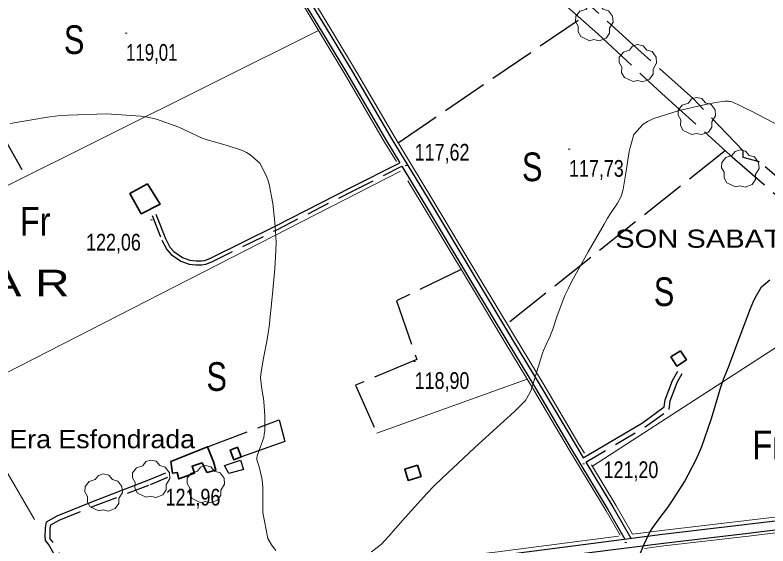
# Model space of a CAD drawing. Extents: x 487425 to 492029, y 4383576 to 4386788.
# Drawn here: x 489030 to 489424, y 4385465.2 to 4385743 of the extents above; entities that cross this region are included whole.
import ezdxf
from ezdxf.enums import TextEntityAlignment as Align

# ---------------------------------------------------------------- set-up
doc = ezdxf.new("R2010")
doc.units = 0
doc.header["$LTSCALE"] = 4
doc.linetypes.add('LONG_DASHED', pattern=[7.5, 6, -1.5])
doc.linetypes.add('MEDIUM_DASHED', pattern=[4.5, 3, -1.5])
for name, color, linetype, lineweight in [('21', 7, 'Continuous', 25), ('25', 7, 'LONG_DASHED', 25), ('29', 7, 'Continuous', 13), ('36', 7, 'Continuous', 25), ('38', 7, 'Continuous', 25), ('47', 7, 'Continuous', 35), ('51', 7, 'Continuous', 13), ('7', 7, 'Continuous', 13), ('8', 7, 'Continuous', 25), ('9', 7, 'Continuous', 13)]:
    doc.layers.add(name, color=color, linetype=linetype, lineweight=lineweight)
doc.layers.add('31', color=7, linetype='Continuous')
doc.layers.add('5', color=7, linetype='Continuous')

msp = doc.modelspace()

# ---------------------------------------------------------------- linework, layer by layer
at = {"layer": '21'}
msp.add_lwpolyline([(489139.64, 4385507.26), (489147.92, 4385510.02), (489149.59, 4385505.27), (489141.84, 4385503.18)], close=True, dxfattribs=at)
at = {"layer": '25'}
for p, q in [((489230.49, 4385676.18), (489325.89, 4385741.14)), ((489401.74, 4385672.05), (489287.47, 4385581.38))]:
    msp.add_line(p, q, dxfattribs=at)
for points in [[(489440.72, 4385647.8), (489419.55, 4385666.12), (489411.02, 4385668.4), (489411.06, 4385671.92), (489385.11, 4385699.07), (489357.64, 4385723.62), (489317.54, 4385760.31), (489289.47, 4385785.39), (489257.02, 4385815.16), (489220.69, 4385845.74), (489191.36, 4385872.85), (489168.69, 4385891.87), (489144.7, 4385919.22), (489122.97, 4385941.6), (489239.75, 4386043.95), (489321.93, 4386119.99), (489486.42, 4385943.37)], [(489115.71, 4385929.31), (489159.69, 4385891.74), (489196.81, 4385857.49), (489250.5, 4385809.01), (489294.68, 4385768.67), (489335.01, 4385733.1), (489368.49, 4385701.89), (489404.14, 4385669.9), (489456.29, 4385624.52), (489481.26, 4385603.45)], [(489142.46, 4385812.11), (488991.66, 4385734.98), (489035.67, 4385658.64)], [(489263.48, 4385609.86), (489229.67, 4385593.49), (489240.2, 4385562.68), (489208.24, 4385549.32), (489219.72, 4385523.38)], [(489128.97, 4385516.4), (489168.19, 4385531.17), (489171.14, 4385519.88), (489148.32, 4385511.73)]]:
    msp.add_lwpolyline(points, dxfattribs=at)
at = {"layer": '29'}
for points in [[(489330.6, 4385729.56), (489326.06, 4385731.68), (489324.65, 4385734.22), (489324.75, 4385737.2), (489323.38, 4385739.61), (489323.42, 4385742.36), (489325.58, 4385744.96), (489328.77, 4385745.96), (489330.42, 4385748.15), (489332.99, 4385748.98), (489335.85, 4385748.33), (489337.8, 4385746.06), (489340.61, 4385745.24), (489342.74, 4385742.39), (489342.98, 4385739.26), (489341.1, 4385736.11), (489341.1, 4385733.43), (489339.28, 4385730.82), (489335.66, 4385729.48), (489332.89, 4385730.11)], [(489353.39, 4385708.15), (489348.85, 4385710.27), (489347.44, 4385712.81), (489347.54, 4385715.79), (489346.17, 4385718.2), (489346.21, 4385720.95), (489348.37, 4385723.55), (489351.56, 4385724.55), (489353.21, 4385726.74), (489355.78, 4385727.57), (489358.64, 4385726.92), (489360.59, 4385724.65), (489363.4, 4385723.83), (489365.53, 4385720.98), (489365.77, 4385717.85), (489363.89, 4385714.7), (489363.89, 4385712.02), (489362.07, 4385709.41), (489358.45, 4385708.07), (489355.68, 4385708.7)], [(489384.21, 4385680.49), (489379.67, 4385682.61), (489378.26, 4385685.15), (489378.36, 4385688.13), (489376.99, 4385690.54), (489377.03, 4385693.29), (489379.19, 4385695.89), (489382.38, 4385696.89), (489384.03, 4385699.08), (489386.6, 4385699.91), (489389.46, 4385699.26), (489391.41, 4385696.99), (489394.22, 4385696.17), (489396.35, 4385693.32), (489396.59, 4385690.19), (489394.71, 4385687.04), (489394.71, 4385684.36), (489392.89, 4385681.75), (489389.27, 4385680.41), (489386.5, 4385681.04)], [(489407, 4385653.07), (489402.46, 4385655.19), (489401.05, 4385657.73), (489401.15, 4385660.71), (489399.78, 4385663.12), (489399.82, 4385665.87), (489401.98, 4385668.47), (489405.17, 4385669.47), (489406.82, 4385671.66), (489409.39, 4385672.49), (489412.25, 4385671.84), (489414.2, 4385669.57), (489417.01, 4385668.75), (489419.14, 4385665.9), (489419.38, 4385662.77), (489417.5, 4385659.62), (489417.5, 4385656.94), (489415.68, 4385654.33), (489412.06, 4385652.99), (489409.29, 4385653.62)], [(489098.62, 4385490.7), (489094.08, 4385492.82), (489092.67, 4385495.36), (489092.77, 4385498.34), (489091.4, 4385500.75), (489091.44, 4385503.5), (489093.6, 4385506.1), (489096.79, 4385507.1), (489098.44, 4385509.29), (489101.01, 4385510.12), (489103.87, 4385509.47), (489105.82, 4385507.2), (489108.63, 4385506.38), (489110.76, 4385503.53), (489111, 4385500.4), (489109.12, 4385497.25), (489109.12, 4385494.57), (489107.3, 4385491.96), (489103.68, 4385490.62), (489100.91, 4385491.25)], [(489127.24, 4385487.83), (489122.7, 4385489.95), (489121.29, 4385492.49), (489121.39, 4385495.47), (489120.02, 4385497.88), (489120.06, 4385500.63), (489122.22, 4385503.23), (489125.41, 4385504.23), (489127.06, 4385506.42), (489129.63, 4385507.25), (489132.49, 4385506.6), (489134.44, 4385504.33), (489137.25, 4385503.51), (489139.38, 4385500.66), (489139.62, 4385497.53), (489137.74, 4385494.38), (489137.74, 4385491.7), (489135.92, 4385489.09), (489132.3, 4385487.75), (489129.53, 4385488.38)], [(489073.78, 4385483.49), (489069.24, 4385485.61), (489067.83, 4385488.15), (489067.93, 4385491.13), (489066.56, 4385493.54), (489066.6, 4385496.29), (489068.76, 4385498.89), (489071.95, 4385499.89), (489073.6, 4385502.08), (489076.17, 4385502.91), (489079.03, 4385502.26), (489080.98, 4385499.99), (489083.79, 4385499.17), (489085.92, 4385496.32), (489086.16, 4385493.19), (489084.28, 4385490.04), (489084.28, 4385487.36), (489082.46, 4385484.75), (489078.84, 4385483.41), (489076.07, 4385484.04)]]:
    msp.add_lwpolyline(points, close=True, dxfattribs=at)
at = {"layer": '36'}
for points in [[(489281.47, 4385459.94), (489327.29, 4385465.95), (489368.77, 4385471.33), (489413.1, 4385476.52), (489451.09, 4385481.12), (489465.77, 4385483.2), (489481.59, 4385484.6), (489488.9, 4385485.86), (489497.14, 4385486.32), (489505.02, 4385487.33), (489519.98, 4385489.49), (489545.69, 4385492.34), (489575.79, 4385496.13), (489620.25, 4385502.45), (489667.37, 4385509.94), (489711.04, 4385516.12), (489752.58, 4385522.55), (489794.27, 4385529.5), (489845.5, 4385537.62), (489881.67, 4385542.39)], [(489327.89, 4385461.33), (489369.34, 4385466.71), (489413.65, 4385471.9), (489451.69, 4385476.5), (489466.31, 4385478.58), (489482.19, 4385479.98), (489489.43, 4385481.23), (489497.56, 4385481.67), (489505.65, 4385482.71), (489520.57, 4385484.87), (489546.24, 4385487.72), (489576.41, 4385491.51), (489620.94, 4385497.84), (489668.06, 4385505.33), (489711.72, 4385511.51), (489753.31, 4385517.94), (489795.03, 4385524.9), (489846.17, 4385533.01), (489882.27, 4385537.77)]]:
    msp.add_lwpolyline(points, dxfattribs=at)
at = {"layer": '38'}
for points in [[(489110.22, 4385925.95), (489110.66, 4385920.71), (489111.24, 4385912.05), (489111.46, 4385905.23), (489111.37, 4385897.37), (489111.4, 4385892.88), (489111.79, 4385886.68), (489112.87, 4385881.22), (489114.23, 4385873.84), (489116.73, 4385865.29), (489118.9, 4385858.42), (489120.71, 4385852.64), (489121.84, 4385848.89), (489125.24, 4385841.78), (489133.79, 4385828.08), (489144.02, 4385811.83), (489152.62, 4385797.75), (489160.99, 4385783.12), (489171.53, 4385764.8), (489183.26, 4385746.28), (489192.23, 4385731.42), (489204.59, 4385710.88), (489224.39, 4385677.11), (489231.34, 4385665.63)], [(489185.74, 4385747.81), (489194.72, 4385732.92), (489207.1, 4385712.37), (489226.9, 4385678.61), (489246.11, 4385646.88), (489271.29, 4385604.73), (489290.36, 4385573.08), (489304.87, 4385549.21), (489323.57, 4385517.56), (489327.36, 4385511.27)], [(489103.71, 4385638.88), (489108.65, 4385626.12), (489111.07, 4385621.52), (489113.13, 4385619.19), (489117.62, 4385616.06), (489121.49, 4385614.67), (489124.76, 4385614.35), (489127.5, 4385614.32), (489129.33, 4385614.57), (489132.2, 4385615.75), (489166.42, 4385632.67), (489205.73, 4385652.7), (489231.34, 4385665.63)], [(489232.41, 4385663.88), (489243.62, 4385645.38), (489268.8, 4385603.23), (489287.87, 4385571.57), (489302.38, 4385547.71), (489321.06, 4385516.06), (489340.28, 4385484.2), (489349.13, 4385468.78)], [(489327.36, 4385511.27), (489358.3, 4385529.64), (489369.78, 4385538.05), (489370.22, 4385541.69), (489374.11, 4385551.76), (489376.77, 4385556.62)], [(489328.72, 4385509.01), (489342.79, 4385485.68), (489352.25, 4385469.19)], [(489065.07, 4385435.14), (489047.55, 4385466.08), (489045.9, 4385468.02), (489045.84, 4385470.57), (489045.88, 4385473.82), (489045.89, 4385474.7), (489046.52, 4385477.78), (489052.06, 4385480.86), (489071.07, 4385488.63), (489099.93, 4385499.7), (489108.96, 4385503.42)]]:
    msp.add_lwpolyline(points, dxfattribs=at)
at = {"layer": '38', "linetype": 'MEDIUM_DASHED'}
for points in [[(489101.8, 4385638.14), (489106.79, 4385625.27), (489109.37, 4385620.34), (489111.76, 4385617.66), (489116.67, 4385614.22), (489121.04, 4385612.66), (489124.65, 4385612.3), (489127.63, 4385612.27), (489129.87, 4385612.58), (489133.05, 4385613.89), (489167.33, 4385630.85), (489206.66, 4385650.88), (489232.41, 4385663.88)], [(489328.72, 4385509.01), (489359.76, 4385527.43), (489372.27, 4385536.59), (489372.81, 4385541.04), (489376.52, 4385550.64), (489379.09, 4385555.35)], [(489067.91, 4385435.52), (489049.59, 4385467.5), (489048.36, 4385468.96), (489048.32, 4385470.59), (489048.36, 4385473.79), (489048.37, 4385474.43), (489048.72, 4385476.16), (489053.14, 4385478.61), (489071.99, 4385486.32), (489100.85, 4385497.39), (489109.9, 4385501.13)]]:
    msp.add_lwpolyline(points, dxfattribs=at)
at = {"layer": '47'}
for points in [[(489099.23, 4385654.69), (489105.93, 4385644.11), (489096.05, 4385639.04), (489090.09, 4385649.69)], [(489378.21, 4385567.34), (489373.19, 4385564.1), (489376.32, 4385559.26), (489381.34, 4385562.5)], [(489111.45, 4385509.38), (489130.75, 4385517.11), (489133.81, 4385509.2), (489135.03, 4385504.91), (489130.37, 4385503.69), (489127.87, 4385508.59), (489122.68, 4385506.93), (489123.91, 4385503.31), (489115.78, 4385500.25), (489114.76, 4385503.64), (489112.43, 4385503.22)], [(489146.42, 4385516.79), (489148.32, 4385511.73), (489144.47, 4385510.28), (489142.57, 4385515.34)], [(489240.62, 4385507.39), (489233.96, 4385505.28), (489235.8, 4385499.49), (489242.46, 4385501.6)]]:
    msp.add_lwpolyline(points, close=True, dxfattribs=at)
at = {"layer": '51'}
for p, q in [((489188.8, 4385734.84), (488956.26, 4385619.12)), ((489481.26, 4385603.45), (489332.15, 4385506.85)), ((489219.4, 4385524.12), (489298.08, 4385552.53))]:
    msp.add_line(p, q, dxfattribs=at)
for points in [[(489229.57, 4385666.3), (489223.38, 4385676.51), (489203.58, 4385710.28), (489191.22, 4385730.81), (489182.26, 4385745.66), (489170.52, 4385764.19), (489159.97, 4385782.54), (489151.61, 4385797.15), (489143.02, 4385811.21), (489132.79, 4385827.46), (489124.21, 4385841.21), (489120.74, 4385848.46), (489119.59, 4385852.3), (489117.78, 4385858.07), (489115.61, 4385864.95), (489113.09, 4385873.57), (489111.72, 4385881), (489110.62, 4385886.53), (489110.23, 4385892.84), (489110.2, 4385897.37), (489110.29, 4385905.22), (489110.07, 4385911.99), (489109.49, 4385920.62), (489109.31, 4385922.77)], [(488777.96, 4385916.34), (488806.25, 4385870.86), (488848.74, 4385800.38), (488874.73, 4385757.32), (488910.35, 4385697.05), (488957.16, 4385617.59), (489002.92, 4385544.3), (489231.79, 4385661.28)], [(489328, 4385513.72), (489325.12, 4385518.49), (489306.42, 4385550.14), (489291.91, 4385574.02), (489272.84, 4385605.66), (489247.66, 4385647.81), (489228.46, 4385679.54), (489208.66, 4385713.3), (489196.27, 4385733.85), (489187.28, 4385748.77)], [(489235.62, 4385656.32), (489242.61, 4385644.77), (489267.79, 4385602.63), (489286.87, 4385570.96), (489301.37, 4385547.11), (489320.05, 4385515.46), (489339.27, 4385483.6), (489346.61, 4385470.82)], [(488871.33, 4385429.34), (489021.81, 4385510.25), (489040.21, 4385478.98)], [(489331.67, 4385507.63), (489344.35, 4385486.6), (489353.16, 4385471.27)], [(489594.86, 4385492.56), (489576.62, 4385489.96), (489546.42, 4385486.17), (489520.77, 4385483.32), (489505.86, 4385481.17), (489497.7, 4385480.12), (489489.61, 4385479.68), (489482.39, 4385478.43), (489466.49, 4385477.03), (489451.89, 4385474.95), (489413.83, 4385470.35), (489369.53, 4385465.16), (489359.35, 4385463.84)], [(489460.62, 4385484.44), (489450.84, 4385483.05), (489412.87, 4385478.46), (489368.53, 4385473.27), (489353.16, 4385471.27)], [(489345.87, 4385470.33), (489327.04, 4385467.88), (489281.24, 4385461.88), (489207.26, 4385453.64), (489133.26, 4385444.73), (489073.8, 4385438.06), (489069.42, 4385437.59)]]:
    msp.add_lwpolyline(points, dxfattribs=at)
at = {"layer": '7'}
for p, q in [((489087.62, 4385733.44), (489088.62, 4385733.44)), ((489319.42, 4385672.73), (489320.42, 4385672.73)), ((489234.1, 4385664.18), (489235.1, 4385664.18)), ((489100.84, 4385635.83), (489101.84, 4385635.83)), ((489238.64, 4385561.72), (489239.64, 4385561.72)), ((489327.08, 4385508.12), (489328.08, 4385508.12)), ((489108.3, 4385500.71), (489109.3, 4385500.71)), ((489349.19, 4385466.98), (489350.19, 4385466.98))]:
    msp.add_line(p, q, dxfattribs=at)
at = {"layer": '8'}
for points in [[(489399.71, 4385549.27), (489400.97, 4385552.83), (489402.52, 4385556.61), (489403.35, 4385558.79), (489404.35, 4385561.46), (489409.4, 4385575.18), (489414.87, 4385589.4), (489416.14, 4385592.39), (489417.3, 4385594.95), (489420.6, 4385600.77), (489424.98, 4385604.45)], [(489356.65, 4385459.83), (489359.29, 4385466.2), (489361.66, 4385471.42), (489362.46, 4385472.84), (489363.33, 4385474.25), (489367.03, 4385479.29), (489371.57, 4385485.29), (489372.99, 4385487.32), (489374.46, 4385489.51), (489380.35, 4385498.72), (489386.35, 4385510.05), (489387.9, 4385513.57), (489389.4, 4385517.26), (489394.42, 4385531.95), (489398.29, 4385544.74), (489399.07, 4385547.24), (489399.71, 4385549.27)]]:
    msp.add_lwpolyline(points, dxfattribs=at)
at = {"layer": '9'}
for points in [[(489225.51, 4385470.08), (489234.1, 4385480.01), (489245.59, 4385492.8), (489249.4, 4385496.68), (489253.48, 4385500.72), (489270.5, 4385516.57), (489286.03, 4385530.61), (489289.18, 4385533.52), (489291.82, 4385535.99), (489297.21, 4385541.38), (489299.41, 4385545.27), (489300.05, 4385546.8), (489300.7, 4385548.53), (489303.14, 4385556.43), (489305.45, 4385564.3), (489306.02, 4385566.01), (489306.56, 4385567.52), (489308.27, 4385571.29), (489310.01, 4385574.98), (489310.58, 4385576.44), (489311.18, 4385578.09), (489313.64, 4385585.66), (489317.76, 4385596.15), (489319.41, 4385599.66), (489321.27, 4385603.42), (489329.85, 4385619.15), (489338.32, 4385633.64), (489340.12, 4385636.62), (489341.68, 4385639.15), (489345.35, 4385644.54), (489347.3, 4385648.45), (489347.77, 4385650.04), (489348.22, 4385651.86), (489349.62, 4385660.26), (489350.99, 4385669.34), (489351.43, 4385671.58), (489351.89, 4385673.71), (489353.75, 4385680.41), (489358.63, 4385685.96), (489360.99, 4385687.35), (489363.79, 4385688.69), (489377.55, 4385693.02), (489391.34, 4385696.17), (489394.16, 4385696.76), (489396.54, 4385697.24), (489401.54, 4385697.96), (489403.44, 4385697.86), (489403.87, 4385697.82), (489404.27, 4385697.78), (489405.36, 4385697.59), (489409.66, 4385695.54), (489412.07, 4385694.32), (489415.02, 4385692.81), (489430.09, 4385685.04)], [(489027.41, 4385686.16), (489046.93, 4385689.55), (489052.39, 4385690.17), (489057.87, 4385690.66), (489077.85, 4385691.28), (489095.89, 4385690.05), (489100.15, 4385689.37), (489104.09, 4385688.54), (489115.67, 4385684.31), (489125.24, 4385679.7), (489127.92, 4385678.63), (489130.6, 4385677.66), (489140.39, 4385674.9), (489149.1, 4385672.12), (489151.1, 4385671.14), (489152.93, 4385670.06), (489158.04, 4385665.41), (489161.49, 4385658.99), (489162.27, 4385656.81), (489162.97, 4385654.44), (489164.84, 4385644.43), (489165.95, 4385634.47), (489166.16, 4385632.14), (489166.34, 4385629.99), (489166.63, 4385623.77), (489166.35, 4385616.37), (489166.15, 4385613.48), (489165.9, 4385610.23), (489164.59, 4385595.44), (489162.9, 4385580.08), (489162.41, 4385576.46), (489161.92, 4385573.13), (489160.1, 4385563.4), (489158.77, 4385556.33), (489158.6, 4385554.67), (489158.51, 4385553.14), (489158.89, 4385548.7), (489159.74, 4385544.14), (489159.95, 4385542.53), (489160.14, 4385540.78), (489160.73, 4385533.22), (489160.67, 4385525.5), (489160.45, 4385523.64), (489160.14, 4385521.91), (489158.28, 4385516.68), (489156.72, 4385512.42), (489156.59, 4385511.3), (489156.59, 4385510.22), (489157.7, 4385506.51), (489159.2, 4385500.7), (489159.44, 4385498.29), (489159.62, 4385495.53), (489159.65, 4385482.64), (489162.33, 4385469.03), (489164.18, 4385465.8), (489166.5, 4385462.82)], [(489216.59, 4385462.07), (489221.71, 4385466.19), (489223.52, 4385467.99), (489225.51, 4385470.08)]]:
    msp.add_lwpolyline(points, dxfattribs=at)

# ---------------------------------------------------------------- texts
at = {"layer": '31'}
for s, width, p in [('S', 0.8, (489060.93, 4385722.61)), ('S', 0.8, (489300.64, 4385656.06)), ('Fr', 0.85, (489040.57, 4385627.59)), ('S', 0.8, (489369.65, 4385590.72)), ('S', 0.8, (489135.51, 4385546.33)), ('S', 0.8, (489135.51, 4385546.33)), ('S', 0.8, (489135.51, 4385546.33)), ('Fr', 0.85, (489423.86, 4385510.58))]:
    msp.add_text(s, height=15, dxfattribs=dict(at, width=width)).set_placement(p, align=Align.CENTER)
at = {"layer": '5'}
for s, height, width, p in [('SON SABATER', 9.5, 1.2, (489452.49, 4385621.22)), ('E S   V E L A R', 13.99, 1.35, (489058.61, 4385595.74)), ("s'Era Esfondrada", 9.5, 1.1, (489124.18, 4385516.33))]:
    msp.add_text(s, height=height, dxfattribs=dict(at, width=width)).set_placement(p, align=Align.RIGHT)
at = {"layer": '7'}
for s, width, p in [('119,01', 0.75, (489088.12, 4385719.07)), ('117,62', 0.8, (489239.16, 4385666.83)), ('117,73', 0.8, (489319.92, 4385658.36)), ('122,06', 0.8, (489067.18, 4385619.78)), ('118,90', 0.8, (489239.14, 4385547.35)), ('121,20', 0.8, (489338.01, 4385500.7)), ('121,96', 0.8, (489108.8, 4385486.34))]:
    msp.add_text(s, height=8.75, dxfattribs=dict(at, width=width)).set_placement(p)

doc.saveas('drawing.dxf')
